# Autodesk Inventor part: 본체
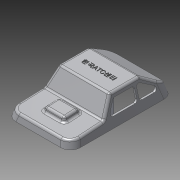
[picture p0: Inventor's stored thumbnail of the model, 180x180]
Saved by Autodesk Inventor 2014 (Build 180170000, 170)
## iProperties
Created: 2015-05
Part Number: 본체
Material: 알루미늄 6061
Document SubType Name: Modeling
Designer: Administrator
Density: 2.71 g/cm^3
Appearance: 알루미늄 - 평지
Mass: 76.5368 g
Surface Area: 288.965 cm^2
Volume: 28.2424 cm^3
Author: Administrator
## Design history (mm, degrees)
sketch "스케치2"
  geometry: L1 (61, 0)-(-61, 0); L2 (61, 0)-(61, 8); L3 (61, 8)-(58.826, 8.114); L4 (19, 10.201)-(6.628, 30); L5 (6.628, 30)-(-28.321, 30); L6 (-28.321, 30)-(-58.321, 10); L7 (-61, 8.214)-(-61, 0); L8 (58.826, 8.114)-(61, 0); L9 (58.826, 8.114)-(19, 10.201); L10 (-58.321, 10)-(-61, 0); L11 (-58.321, 10)-(-61, 8.214); 2 further points
  constraints: 22 end point, 2 collinear, 2 perpendicular, 1 coincident, 1 horizontal, 1 midpoint, 1 parallel
  dimensions: "d3" = 105 deg angle of L8 L1; "d5" = 125 deg angle of L9 L4; "d6" = 105 deg angle of L1 L10; "d7" = 30 vertical distance of L5.end L1.end; "d8" = 20 vertical distance of L5.end L6.end; "d9" = 30 horizontal distance of L6.end L5.end; "d13" = 3 deg angle of L1 L9; "d14" = 8 distance of L1.start L2.end; "d15" = 42 horizontal distance of L4.start L2.end; "d70" = 122 distance of L1.start L1.end
extrude "돌출1" new body sketch "스케치2" stored distance "d11" = 76; taper "d12" = 0 deg
node "작업 평면1"
sketch "스케치5"
  geometry: L1 (-36.139, 9)-(-36.139, 61) reference; L2 (0, 73)-(-26.676, 73) reference; L3 (-26.676, -3)-(0, -3) reference; L4 (-40.915, 9)-(-40.915, 61) reference; L5 (-6.649, 48)-(-26.649, 48); L6 (-26.649, 48)-(-26.649, 22); L7 (-26.649, 22)-(-6.649, 22); L8 (-6.649, 22)-(-6.649, 48); L9 (-6.649, 48)-(-26.649, 22); L10 (-26.649, 48)-(-6.649, 22); 5 further points
  constraints: 12 end point, 4 midpoint, 2 parallel, 1 coincident, 1 horizontal, 1 horizontal alignment, 1 perpendicular
  dimensions: "d40" = 20 distance of L6.end L7.end; "d41" = 26 distance of L7.end L5.start
extrude "돌출4" join sketch "스케치5" distance "d42" = 5; taper "d43" = -20 deg
node "작업 평면2"
sketch "스케치7"
  geometry: L1 (38, 8.774)-(38, 0) reference; L2 (38, 27)-(38, 9.936) reference; L3 (38, 7.124)-(38, 9.936) reference; L4 (38, 7.124)-(38, 5.727) reference; L5 (26, 0)-(36, 0) reference; L6 (38, 0)-(28.661, 34.854); L7 (28.661, 34.854)-(38, 34.854); L8 (38, 34.854)-(38, 0); L9 (-38, 9.936)-(-38, 27) reference; L10 (-36, 0)-(-26, 0) reference; L11 (-38, 35.911)-(-38, 0); L12 (-38, 0)-(-28.378, 35.911); L13 (-28.378, 35.911)-(-38, 35.911); 1 further point
  constraints: 12 end point, 2 perpendicular, 2 point on line, 1 parallel
  dimensions: "d57" = 105 deg angle of L5 L6; "d58" = 105 deg angle of L10 L12
extrude "돌출6" cut sketch "스케치7" stored distance "d59" = 5; taper "d60" = 0 deg
fillet "모깎기6" dims "d61" = 12
fillet "모깎기7" dims "d62" = 3
fillet "모깎기8" dims "d63" = 3
fillet "모깎기9" dims "d64" = 3
sketch "스케치8"
  geometry: L1 (18.172, 11.526)-(7.51, 28.59) reference; L2 (4.965, 30)-(-27.412, 30) reference; L3 (-29.076, 29.496)-(-46.796, 17.683) reference; L4 (-57.38, 10.627)-(-46.796, 17.683) reference; L5 (4.738, 23.59)-(10.362, 14.59); L6 (7.818, 10)-(-17.77, 10); L7 (-20.77, 13)-(-20.77, 22); L8 (2.194, 25)-(-17.77, 25); L9 (-26.107, 10)-(-40.683, 10); L10 (-23.107, 13)-(-23.107, 22.148); L11 (-27.702, 24.689)-(-42.278, 15.541); A1 r 3 centre (4.965, 27) between (7.51, 28.59) and (4.965, 30) reference; A2 r 3 centre (-27.412, 27) between (-27.412, 30) and (-29.076, 29.496) reference; A3 r 3 centre (-17.77, 22) between (-17.77, 25) and (-20.77, 22); A4 r 3 centre (-40.683, 13) between (-42.278, 15.541) and (-40.683, 10); A5 r 3 centre (-26.107, 22.148) between (-23.107, 22.148) and (-27.702, 24.689); A6 r 3 centre (-17.77, 13) between (-20.77, 13) and (-17.77, 10); A7 r 3 centre (-26.107, 13) between (-26.107, 10) and (-23.107, 13); A8 r 3 centre (7.818, 13) between (7.818, 10) and (10.362, 14.59); A9 r 3 centre (2.194, 22) between (4.738, 23.59) and (2.194, 25); 8 further points
  constraints: 14 end point, 14 point on circle, 14 tangent, 12 point on line, 7 centre point, 4 equal radius, 3 perpendicular, 2 parallel, 1 collinear
  dimensions: "d66" = 5 distance between parallel lines of L5 L1; "d67" = 5 distance between parallel lines of L8 L2; "d69" = 15 distance of point (-20.77, 10) point (-20.77, 25); "d80" = 28 distance of point (-51.107, 10) point (-23.107, 10); "d90" = 3 radius of A3; "d91" = 3 radius of A4; "d92" = 5 distance of L3.end L11.end; "d93" = 5 distance of L3.start L11.start; "d94" = 34 distance of point (13.23, 10) point (-20.77, 10); "d95" = 3 radius of A6
feature "쉘2" dims "d96" = 2
extrude "돌출7" cut sketch "스케치8" stored distance "d97" = 5; taper "d98" = 0 deg
sketch "스케치10"
  geometry: L1 (-45, 1)-(-35, 1); L2 (-35, 1)-(-35, -1); L3 (-35, -1)-(-45, -1); L4 (-45, -1)-(-45, 1); L5 (-45, 1)-(-35, -1); L6 (-35, 1)-(-45, -1); L7 (-5, 23)-(5, 23); L8 (5, 23)-(5, 21); L9 (5, 21)-(-5, 21); L10 (-5, 21)-(-5, 23); L11 (-5, 23)-(5, 21); L12 (5, 23)-(-5, 21); L13 (35, 1)-(45, 1); L14 (45, 1)-(45, -1); L15 (45, -1)-(35, -1); L16 (35, -1)-(35, 1); L17 (35, 1)-(45, -1); L18 (45, 1)-(35, -1); L19 (-5, -21)-(5, -21); L20 (5, -21)-(5, -23); L21 (5, -23)-(-5, -23); L22 (-5, -23)-(-5, -21); L23 (-5, -21)-(5, -23); L24 (5, -21)-(-5, -23); C1 r 3 at (-40, 0); C2 r 3 at (40, 0); C3 r 3 at (0, -22); C4 r 3 at (0, 22); 1 further point
  constraints: 48 end point, 8 midpoint, 8 parallel, 4 centre point, 4 horizontal, 4 perpendicular
  dimensions: "d99" = 6 diameter of C1; "d100" = 40 distance of C1.centre point (0, 0); "d101" = 6 diameter of C2; "d102" = 40 distance of point (0, 0) C2.centre; "d103" = 6 diameter of C3; "d104" = 22 distance of C3.centre point (0, 0); "d105" = 6 diameter of C4; "d106" = 44 distance of C3.centre C4.centre; "d109" = 2 distance of L1.end L2.end; "d110" = 10 distance of L2.end L3.end; "d111" = 10 distance of L20.end L21.end; "d112" = 2 distance of L19.end L20.end; "d113" = 10 distance of L14.end L15.end; "d114" = 2 distance of L13.end L14.end; "d115" = 10 distance of L8.end L9.end; "d116" = 2 distance of L7.end L8.end
extrude "돌출8" join sketch "스케치10" stored distance "d107" = 1; taper "d108" = 0 deg
extrude "돌출9" join sketch "스케치10" stored distance "d117" = 1; taper "d118" = 0 deg
sketch "스케치11"
  geometry: L1 (42.828, -1)-(45, -1) reference; L2 (45, -1)-(45, 1) reference; L3 (45, 1)-(42.828, 1) reference; L4 (37.172, 1)-(35, 1) reference; L5 (35, 1)-(35, -1) reference; L6 (35, -1)-(37.172, -1) reference; L7 (2.828, 21)-(5, 21) reference; L8 (5, 21)-(5, 23) reference; L9 (5, 23)-(2.828, 23) reference; L10 (-2.828, 23)-(-5, 23) reference; L11 (-5, 23)-(-5, 21) reference; L12 (-5, 21)-(-2.828, 21) reference; L13 (2.828, -23)-(5, -23) reference; L14 (5, -23)-(5, -21) reference; L15 (5, -21)-(2.828, -21) reference; L16 (-2.828, -21)-(-5, -21) reference; L17 (-5, -21)-(-5, -23) reference; L18 (-5, -23)-(-2.828, -23) reference; L19 (-42.828, 1)-(-45, 1) reference; L20 (-45, 1)-(-45, -1) reference; L21 (-45, -1)-(-42.828, -1) reference; L22 (-37.172, -1)-(-35, -1) reference; L23 (-35, -1)-(-35, 1) reference; L24 (-35, 1)-(-37.172, 1) reference; A1 r 3 centre (40, 0) between (42.828, 1) and (37.172, 1) reference; A2 r 3 centre (40, 0) between (37.172, -1) and (42.828, -1) reference; A3 r 3 centre (0, 22) between (2.828, 23) and (-2.828, 23) reference; A4 r 3 centre (0, 22) between (-2.828, 21) and (2.828, 21) reference; A5 r 3 centre (0, -22) between (2.828, -21) and (-2.828, -21) reference; A6 r 3 centre (0, -22) between (-2.828, -23) and (2.828, -23) reference; A7 r 3 centre (-40, 0) between (-42.828, -1) and (-37.172, -1) reference; A8 r 3 centre (-40, 0) between (-37.172, 1) and (-42.828, 1) reference; 5 further points
  constraints: 4 coincident
  node "투영된 루프1"
  node "투영된 루프2"
  node "투영된 루프3"
sketch "스케치12"
  geometry: L1 (65.965, 54.068)-(65.965, 1.251) reference; 2 further points
  constraints: 1 horizontal alignment, 1 other
  dimensions: "d119" = 50 distance from line of L1 point (15.965, 27.66)
feature "엠보싱1" sketch "스케치12" dims "d3" = 105 deg, "d5" = 125 deg, "d6" = 105 deg, "d7" = 30, "d8" = 20, "d9" = 30, "d13" = 3 deg, "d14" = 8, "d15" = 42, "d43" = -20 deg, "d70" = 122, "d120" = 0.5, "d121" = 0
node "솔리드1"
other parameters: "d24" = 5, "d46" = -59
